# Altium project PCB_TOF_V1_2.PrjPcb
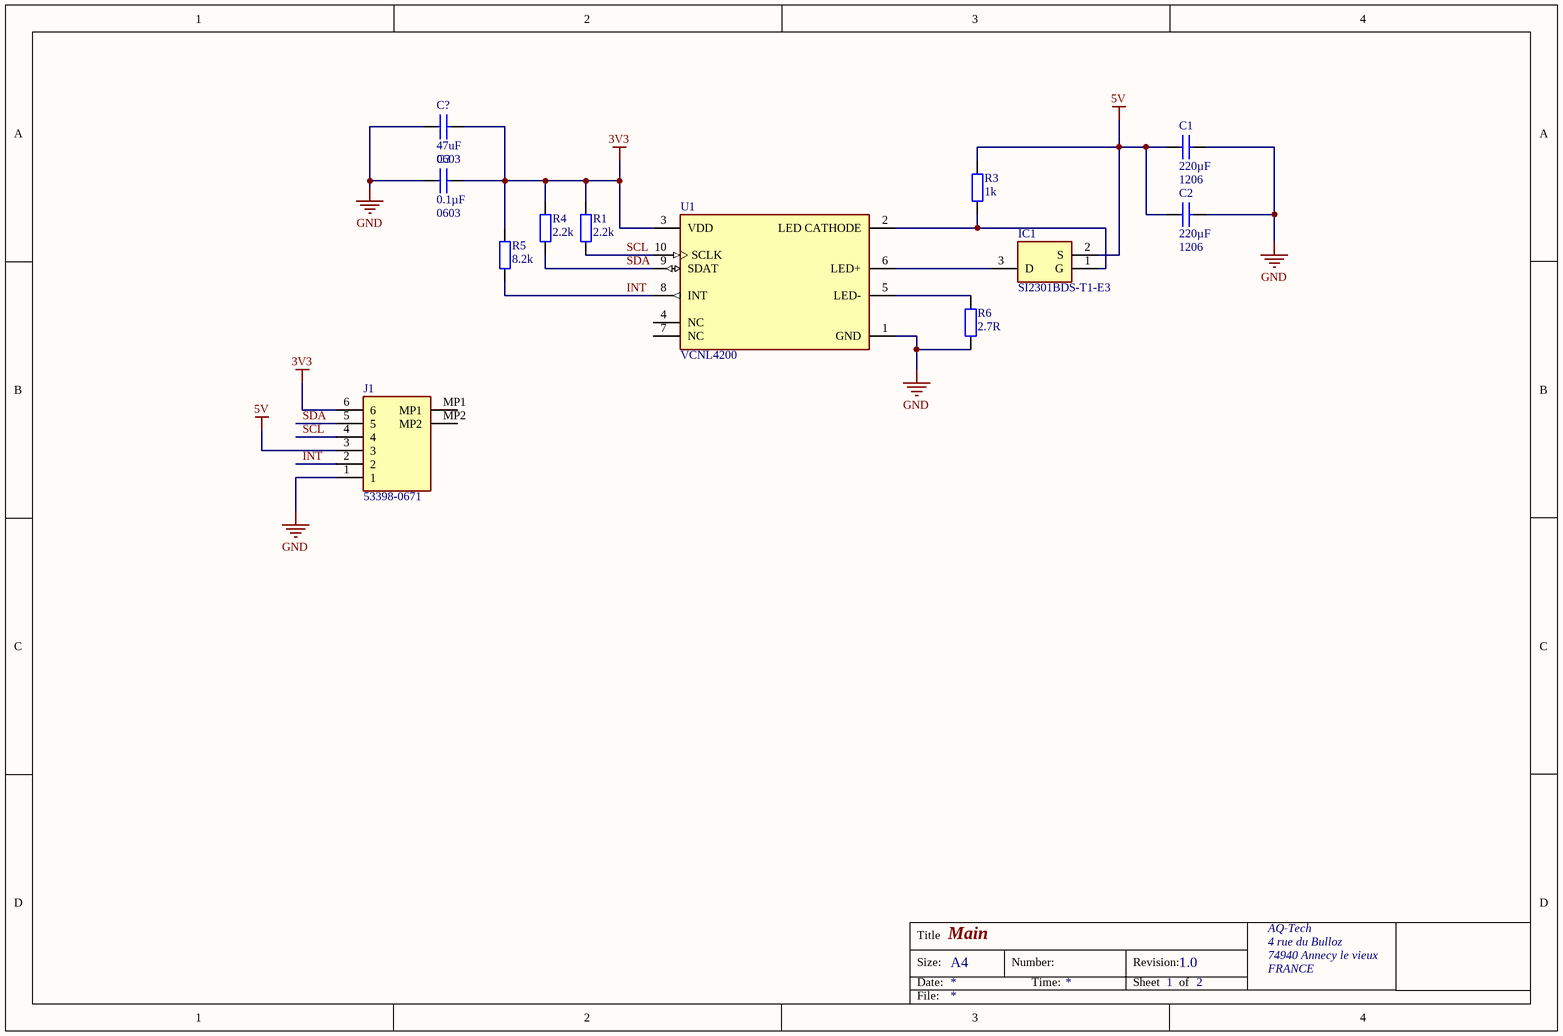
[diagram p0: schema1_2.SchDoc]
1 sheet, 12 parts. Net scope: global (net labels, ports and power ports of the same name join across sheets).
Board file: PCB1_2.PcbDoc

## Sheet schema1_2.SchDoc: DEV-09-17 MERE
size A4; Date: 22/11/2017; Organization: Altium Limited; Address1: L3, 12a Rodborough Rd; Address2: Frenchs Forest; Address3: NSW; Address4: Australia 2086; Revision: 1.0; SheetNumber: 1; SheetTotal: 1; PageSetup: Record=PageOptions¦CenterHorizontal=True¦CenterVertical=True¦PrintScale=0.97¦XCorrection=1.00¦YCorrection=1.00¦PrintKind=0¦BorderSize=5000000¦LeftOffset=0¦BottomOffset=0¦Orientation=2¦PaperLength=1000¦PaperWidth=1000¦Scale=100¦PaperSource=7¦PrintQuality=-3¦MediaType=1¦DitherType=10¦PaperKind=A4¦PrintScaleMode=1

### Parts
C1  220µF  CASE: 1206  [CAP_1206_1H90]
C2  220µF  CASE: 1206  [CAP_1206_1H90]
C3  0.1µF  CASE: 0603  [CAP_0603_0H80]
C?  47uF  CASE: 0603  [CAP_0603_0H80]
IC1  SI2301BDS-T1-E3  [SOT95P237X112-3N]
J1  53398-0671  [533980671]
R1  2.2k  [RES_0603_0H90_2]
R3  1k  [RES_0603_0H90_2]
R4  2.2k  [RES_0603_0H90_2]
R5  8.2k  [RES_0603_0H90_2]
R6  2.7R  [RES_0603_0H90_2]
U1  VCNL4200  [FP-VCNL4200-MFG]

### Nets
3V3: C3.2 C?.2 J1.6 R1.2 R4.2 R5.2 U1.3(VDD)
5V: C1.1 C2.1 IC1.2(S) J1.3 R3.2
GND: C1.2 C2.2 C3.1 C?.1 J1.1 R6.1 U1.1(GND)
INT: J1.2 R5.1 U1.8(INT)
SCL: J1.4 R1.1 U1.10(SCLK)
SDA: J1.5 R4.1 U1.9(SDAT)
NetIC1_1: IC1.1(G) R3.1 U1.2(LED_CATHODE)
NetIC1_3: IC1.3(D) U1.6(LED+)
NetR6_2: R6.2 U1.5(LED-)

Not connected (* = marked no-connect by the designer): J1 MP1 MP2; U1 4(NC) 7(NC)

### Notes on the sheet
- Title
- Size:
- Date:
- Main
- A4
- Number:
- Time:
- Revision:
- Sheet
- 1
- of
- 2
- AQ-Tech
- 4 rue du Bulloz
- 74940 Annecy le vieux
- FRANCE
- File:

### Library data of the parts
C1 = C0603-10µF-X5R-6.3V: Capacitor, Ceramic, 220µF, 1206, 10%, 6.3V, X5R; Ref Fabricant: Generic
C2 = C0603-10µF-X5R-6.3V: Capacitor, Ceramic, 220µF, 0603, 10%, 6.3V, X5R; Ref Fabricant: Generic
C3 = C0603-10µF-X5R-6.3V: Capacitor, Ceramic, 0.1µF, 0603, 10%, 6.3V, X5R; Ref Fabricant: Generic
C? = C0603-10µF-X5R-6.3V: Capacitor, Ceramic, 47µF, 0603, 10%, 6.3V, X5R; Ref Fabricant: Generic
IC1 = SI2301BDS-T1-E3: Integrated Circuit; Manufacturer_Name: Vishay
J1 = 53398-0671: Connector; Manufacturer_Name: Molex
R1 R4 = R0603_120k_1%: Resistor, Thin Film, 2.2k, 1%, 65mW, 0603; Ref Fabricant: Generic; TCR: 100ppm/°C
R3 = R0603_120k_1%: Resistor, Thin Film, 1k, 1%, 65mW, 0603; Ref Fabricant: Generic; TCR: 100ppm/°C
R5 = R0603_120k_1%: Resistor, Thin Film, 8.2k, 1%, 65mW, 0603; Ref Fabricant: Generic; TCR: 100ppm/°C
R6 = R0603_120k_1%: Resistor, Thin Film, 2.7R, 1%, 65mW, 0603; Ref Fabricant: Generic; TCR: 100ppm/°C
U1 = CMP-02530-000006-1: SENSOR OPT 550NM AMBIENT 10SMD; Manufacturer: Vishay; Operating Supply Current: 350uA; Max Supply Voltage: 3.6V; Min Supply Voltage: 2.5V; Sensor Output: I2C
